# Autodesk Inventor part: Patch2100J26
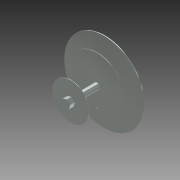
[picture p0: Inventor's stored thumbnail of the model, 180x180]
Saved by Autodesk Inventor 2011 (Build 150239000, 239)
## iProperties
Created: 2014-07
Part Number: Patch2100J26
Document SubType Name: Modeling
Designer: Evgeny
Density: 1 g/cm^3
Author: Evgeny
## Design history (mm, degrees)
sketch "Эскиз1"
  geometry: L1 (28.5, 24.372)-(28.5, -24.372); L2 (-28.5, -24.372)-(-28.5, 24.372); C1 r 1.35 at (0, -26); A1 r 37.5 centre (0, 0) between (28.5, 24.372) and (-28.5, 24.372); A2 r 37.5 centre (0, 0) between (-28.5, -24.372) and (28.5, -24.372); 1 further point
  constraints: 4 end point, 4 point on circle, 3 centre point, 1 coincident, 1 parallel
  dimensions: "d1" = 57 distance between parallel lines of L1 L2; "d2" = 28.5 distance from line of L2 point (0, 0); "d3" = 37.5 radius of A1; "d4" = 37.5 radius of A2; "d5" = 2.7 diameter of C1; "d6" = 26 distance of point (0, 0) C1.centre
extrude "Выдавливание1" new body sketch "Эскиз1" distance "d7" = 0.5; taper "d8" = 0 deg
sketch "Эскиз2"
  geometry: C1 r 4 at (0, 0); A1 r 37.5 centre (0, 0) between (-28.5, -24.372) and (28.5, -24.372) reference
  constraints: 1 centre point, 1 coincident
  dimensions: "d9" = 8 diameter of C1
extrude "Выдавливание2" join sketch "Эскиз2" distance "d10" = 8.9; taper "d11" = 0 deg; dims "d20" = 48
sketch "Эскиз3"
  geometry: C1 r 4 at (0, 0) reference; C2 r 52 at (0, 0); C3 r 4 at (0, -26)
  constraints: 2 centre point, 1 coincident
  dimensions: "d12" = 104 diameter of C2; "d13" = 8 diameter of C3; "d14" = 26 distance of C3.centre C1.centre
extrude "Выдавливание3" join sketch "Эскиз3" distance "d15" = 1; taper "d16" = 0 deg
sketch "Эскиз4"
  geometry: C1 r 4 at (0, 0); A1 r 37.5 centre (0, 0) between (-28.5, -24.372) and (28.5, -24.372) reference
  constraints: 1 centre point, 1 coincident
  dimensions: "d17" = 8 diameter of C1
extrude "Выдавливание4" join sketch "Эскиз4" distance "d18" = 34; taper "d19" = 0 deg
sketch "Эскиз5"
  geometry: C1 r 4 at (0, 0) reference; C2 r 24 at (0, 0)
  constraints: 1 centre point, 1 coincident
  dimensions: "d20" = 48 diameter of C2
extrude "Выдавливание5" join sketch "Эскиз5" distance "d21" = 0.5; taper "d22" = 0 deg
sketch "Эскиз6"
  geometry: L1 (-1.421, -5.596)-(-5.557, -1.567); L2 (-5.557, -1.567)-(-4.136, 4.029); L3 (-4.136, 4.029)-(1.421, 5.596); L4 (1.421, 5.596)-(5.557, 1.567); L5 (5.557, 1.567)-(4.136, -4.029); L6 (4.136, -4.029)-(-1.421, -5.596); C1 r 24 at (0, 0) reference; 1 further point
  constraints: 12 end point, 1 coincident, 13 other
  dimensions: "d24" = 10 distance between parallel lines of L6 L3
extrude "Выдавливание6" join sketch "Эскиз6" distance "d25" = 6; taper "d26" = 0 deg
sketch "Эскиз7"
  geometry: L1 (0, -5.774)-(-5, -2.887); L2 (-5, -2.887)-(-5, 2.887); L3 (-5, 2.887)-(0, 5.774); L4 (0, 5.774)-(5, 2.887); L5 (5, 2.887)-(5, -2.887); L6 (5, -2.887)-(0, -5.774); C1 r 52 at (0, 0) reference; 1 further point
  constraints: 12 end point, 1 coincident, 13 other
  dimensions: "d27" = 10 distance between parallel lines of L5 L2
extrude "Выдавливание7" join sketch "Эскиз7" distance "d28" = 6; taper "d29" = 0 deg
sketch "Эскиз8"
  geometry: C1 r 3 at (0, 0); 1 further point
  constraints: 1 centre point, 1 coincident
  dimensions: "d30" = 6 diameter of C1
extrude "Выдавливание8" join sketch "Эскиз8" distance "d31" = 6; taper "d32" = 0 deg
extrude "Выдавливание9" join sketch "Эскиз1" distance "d33" = 1; taper "d35" = 0 deg; dims "d34" = 9.9, "d36" = 0
node "Твердое тело1"
other parameters: "d0" = 75
